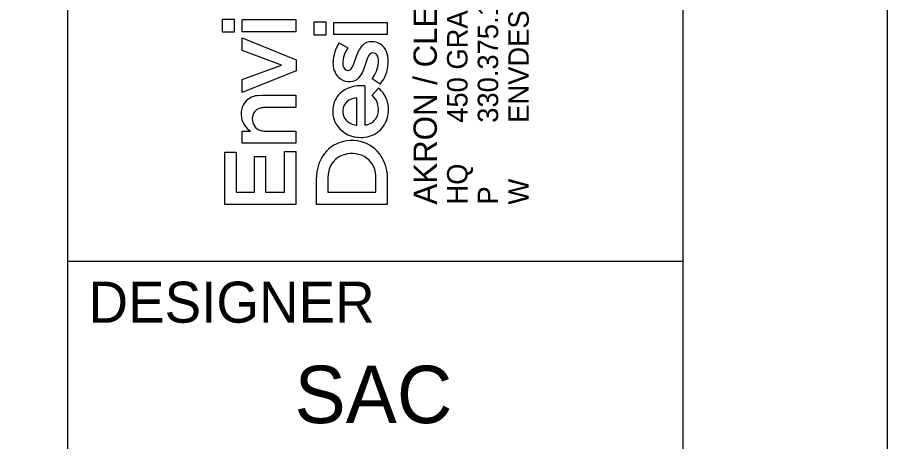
# Model space of a CAD drawing. Extents: x 0 to 34, y 0 to 22.
# Drawn here: x 31.877 to 34, y 2.06 to 3.094 of the extents above; entities that cross this region are included whole.
import ezdxf

# ---------------------------------------------------------------- set-up
doc = ezdxf.new("R2010")
doc.units = 0
for name, color, linetype in [('SH_Border', 7, 'Continuous'), ('SH_Cut_Line', 7, 'Continuous'), ('SH_Data', 7, 'Continuous')]:
    doc.layers.add(name, color=color, linetype=linetype)

msp = doc.modelspace()

# ---------------------------------------------------------------- linework, layer by layer
at = {"layer": 'SH_Border'}
for p, q in [((32, 0.5), (32, 21.5)), ((32, 2.5), (33.5, 2.5))]:
    msp.add_line(p, q, dxfattribs=at)
msp.add_lwpolyline([(1.5, 21.5), (33.5, 21.5), (33.5, 0.5), (1.5, 0.5)], close=True, dxfattribs=at)
at = {"layer": 'SH_Cut_Line'}
msp.add_lwpolyline([(0, 0), (34, 0), (34, 22), (0, 22)], close=True, dxfattribs=at)
at = {"layer": 'SH_Data'}
for p, q in [((32.3771, 3.0582), (32.3771, 3.0903)), ((32.3771, 3.0903), (32.4054, 3.0903)), ((32.4054, 3.0903), (32.4054, 3.0582)), ((32.4254, 3.0594), (32.4254, 3.0893)), ((32.4254, 3.0893), (32.5557, 3.0893)), ((32.5557, 3.0893), (32.5557, 3.0594)), ((32.6005, 3.0511), (32.6005, 3.0832)), ((32.6005, 3.0832), (32.6289, 3.0832)), ((32.6289, 3.0832), (32.6289, 3.0511)), ((32.6489, 3.0523), (32.6489, 3.0822)), ((32.6489, 3.0822), (32.7792, 3.0822)), ((32.7792, 3.0822), (32.7792, 3.0523)), ((32.4054, 3.0582), (32.3771, 3.0582)), ((32.5557, 3.0594), (32.4254, 3.0594)), ((32.4254, 3.0133), (32.4254, 3.0446)), ((32.4254, 3.0446), (32.5567, 2.9913)), ((32.6289, 3.0511), (32.6005, 3.0511)), ((32.7792, 3.0523), (32.6489, 3.0523)), ((32.6615, 3.0321), (32.6827, 3.0203)), ((32.5212, 2.978), (32.4254, 3.0133)), ((32.6967, 2.9787), (32.7048, 3.0026)), ((32.7048, 3.0026), (32.7104, 3.0153)), ((32.7334, 3.001), (32.7298, 2.9933)), ((32.4254, 2.9429), (32.5212, 2.978)), ((32.5567, 2.9913), (32.5567, 2.9644)), ((32.693, 2.9712), (32.6967, 2.9787)), ((32.7298, 2.9933), (32.7221, 2.9688)), ((32.5567, 2.9644), (32.4254, 2.9109)), ((32.7221, 2.9688), (32.7182, 2.9592)), ((32.4254, 2.9109), (32.4254, 2.9429)), ((32.7621, 2.9314), (32.742, 2.9447)), ((32.7245, 2.9275), (32.7246, 2.8319)), ((32.7423, 2.9046), (32.7577, 2.922)), ((32.4644, 2.904), (32.4729, 2.9044)), ((32.4729, 2.9044), (32.5557, 2.9044)), ((32.5557, 2.9044), (32.5557, 2.8746)), ((32.7049, 2.8318), (32.7049, 2.8983)), ((32.5557, 2.8746), (32.4814, 2.8746)), ((32.7036, 2.8317), (32.7049, 2.8318)), ((32.4254, 2.7875), (32.4254, 2.8173)), ((32.4254, 2.8173), (32.4455, 2.8173)), ((32.4822, 2.8173), (32.5557, 2.8173)), ((32.5557, 2.8173), (32.5557, 2.7876)), ((32.5557, 2.7876), (32.4254, 2.7875)), ((32.383, 2.6379), (32.383, 2.766)), ((32.383, 2.766), (32.4101, 2.766)), ((32.4101, 2.766), (32.4101, 2.6683)), ((32.5286, 2.6683), (32.5286, 2.7672)), ((32.5286, 2.7672), (32.5557, 2.7672)), ((32.5557, 2.7672), (32.5557, 2.6379)), ((32.455, 2.6683), (32.455, 2.7549)), ((32.455, 2.7549), (32.4822, 2.7549)), ((32.4822, 2.7549), (32.4822, 2.6683)), ((32.6064, 2.638), (32.6064, 2.704)), ((32.6347, 2.7118), (32.6341, 2.7023)), ((32.6341, 2.7023), (32.6341, 2.6684)), ((32.7515, 2.6683), (32.7515, 2.7024)), ((32.7785, 2.715), (32.7792, 2.7021)), ((32.7792, 2.7021), (32.7792, 2.638)), ((32.4101, 2.6683), (32.455, 2.6683)), ((32.4822, 2.6683), (32.5286, 2.6683)), ((32.6341, 2.6684), (32.7515, 2.6683)), ((32.5557, 2.6379), (32.383, 2.6379)), ((32.7792, 2.638), (32.6064, 2.638))]:
    msp.add_line(p, q, dxfattribs=at)
for points in [[(32.3771, 3.0582), (32.3771, 3.0903), (32.4054, 3.0903), (32.4054, 3.0582)], [(32.4254, 3.0594), (32.4254, 3.0893), (32.5557, 3.0893), (32.5557, 3.0594)], [(32.6005, 3.0511), (32.6005, 3.0832), (32.6289, 3.0832), (32.6289, 3.0511)], [(32.6489, 3.0523), (32.6489, 3.0822), (32.7792, 3.0822), (32.7792, 3.0523)], [(32.4254, 2.9109), (32.4254, 2.9429), (32.5212, 2.978), (32.4254, 3.0133), (32.4254, 3.0446), (32.5567, 2.9913), (32.5567, 2.9644)], [(32.383, 2.6379), (32.383, 2.766), (32.4101, 2.766), (32.4101, 2.6683), (32.455, 2.6683), (32.455, 2.7549), (32.4822, 2.7549), (32.4822, 2.6683), (32.5286, 2.6683), (32.5286, 2.7672), (32.5557, 2.7672), (32.5557, 2.6379)]]:
    msp.add_lwpolyline(points, close=True, dxfattribs=at)
for points in [[(32.6615, 3.0321), (32.6827, 3.0203)], [(32.693, 2.9712), (32.6967, 2.9787), (32.7048, 3.0026), (32.7104, 3.0153)], [(32.7334, 3.001), (32.7298, 2.9933), (32.7221, 2.9688), (32.7182, 2.9592)], [(32.7621, 2.9314), (32.742, 2.9447)], [(32.7245, 2.9275), (32.7246, 2.8319)], [(32.7423, 2.9046), (32.7577, 2.922)], [(32.4644, 2.904), (32.4729, 2.9044), (32.5557, 2.9044), (32.5557, 2.8746), (32.4814, 2.8746)], [(32.7036, 2.8317), (32.7049, 2.8318), (32.7049, 2.8983)], [(32.4254, 2.7875), (32.4254, 2.8173), (32.4455, 2.8173)], [(32.4822, 2.8173), (32.5557, 2.8173), (32.5557, 2.7876), (32.4254, 2.7875)], [(32.7785, 2.715), (32.7792, 2.7021), (32.7792, 2.638), (32.6064, 2.638)], [(32.6064, 2.638), (32.6064, 2.704)], [(32.6347, 2.7118), (32.6341, 2.7023), (32.6341, 2.6684), (32.7515, 2.6683), (32.7515, 2.7024)]]:
    msp.add_lwpolyline(points, dxfattribs=at)
for centre, radius, start, end in [((32.7364, 2.9826), 0.0897, 146.531, 178.7571), ((32.7364, 2.9826), 0.0897, 146.531, 178.7571), ((32.7452, 2.9789), 0.0749, 146.5112, 176.9101), ((32.7452, 2.9789), 0.0749, 146.5112, 176.9101), ((32.7466, 2.9971), 0.0405, 125.5118, 153.4159), ((32.7466, 2.9971), 0.0405, 125.5118, 153.4159), ((32.7406, 3.0026), 0.0326, 80.1719, 122.5197), ((32.7406, 3.0026), 0.0326, 80.1719, 122.5197), ((32.7428, 2.9982), 0.0367, 47.7934, 84.6892), ((32.7428, 2.9982), 0.0367, 47.7934, 84.6892), ((32.7379, 2.9946), 0.0427, 14.9966, 46.2063), ((32.7379, 2.9946), 0.0427, 14.9966, 46.2063), ((32.7438, 2.9963), 0.0114, 76.6609, 155.7053), ((32.7438, 2.9963), 0.0114, 76.6609, 155.7053), ((32.744, 2.9951), 0.0126, 21.5098, 78.5262), ((32.744, 2.9951), 0.0126, 21.5098, 78.5262), ((32.7259, 2.9877), 0.0321, 354.5726, 22.068), ((32.7259, 2.9877), 0.0321, 354.5726, 22.068), ((32.7104, 2.9867), 0.0712, 355.8306, 15.3914), ((32.7104, 2.9867), 0.0712, 355.8306, 15.3914), ((32.6967, 2.9824), 0.0501, 177.5366, 222.7932), ((32.6967, 2.9824), 0.0501, 177.5366, 222.7932), ((32.6931, 2.9823), 0.0228, 178.4747, 211.0868), ((32.6931, 2.9823), 0.0228, 178.4747, 211.0868), ((32.6825, 2.9915), 0.0757, 321.811, 354.7969), ((32.6825, 2.9915), 0.0757, 321.811, 354.7969), ((32.6895, 2.9882), 0.0922, 321.9777, 355.8738), ((32.6895, 2.9882), 0.0922, 321.9777, 355.8738), ((32.6833, 2.9767), 0.0115, 212.2368, 268.3777), ((32.6833, 2.9767), 0.0115, 212.2368, 268.3777), ((32.6834, 2.9759), 0.0107, 267.716, 333.7337), ((32.6834, 2.9759), 0.0107, 267.716, 333.7337), ((32.681, 2.9758), 0.0408, 308.0877, 335.9874), ((32.681, 2.9758), 0.0408, 308.0877, 335.9874), ((32.686, 2.9753), 0.0375, 225.9854, 302.4797), ((32.686, 2.9753), 0.0375, 225.9854, 302.4797), ((32.7024, 2.8691), 0.0558, 118.8308, 160.6244), ((32.7024, 2.8691), 0.0558, 118.8308, 160.6244), ((32.7152, 2.8441), 0.0838, 83.615, 118.2876), ((32.7152, 2.8441), 0.0838, 83.615, 118.2876), ((32.7174, 2.8717), 0.0644, 13.5336, 51.3615), ((32.7174, 2.8717), 0.0644, 13.5336, 51.3615), ((32.4635, 2.8626), 0.0402, 132.2219, 161.6818), ((32.4635, 2.8626), 0.0402, 132.2219, 161.6818), ((32.4687, 2.8543), 0.0499, 94.9696, 130.2225), ((32.4687, 2.8543), 0.0499, 94.9696, 130.2225), ((32.7005, 2.8663), 0.0298, 132.9851, 177.179), ((32.7005, 2.8663), 0.0298, 132.9851, 177.179), ((32.7079, 2.8561), 0.0424, 94.008, 130.8817), ((32.7079, 2.8561), 0.0424, 94.008, 130.8817), ((32.7038, 2.8656), 0.0549, 19.0357, 45.4406), ((32.7038, 2.8656), 0.0549, 19.0357, 45.4406), ((32.4787, 2.8582), 0.056, 162.2736, 187.7919), ((32.4787, 2.8582), 0.056, 162.2736, 187.7919), ((32.4748, 2.8487), 0.025, 103.6865, 182.2187), ((32.4748, 2.8487), 0.025, 103.6865, 182.2187), ((32.4811, 2.8286), 0.046, 89.6049, 105.3284), ((32.4811, 2.8286), 0.046, 89.6049, 105.3284), ((32.7104, 2.8661), 0.0644, 160.5201, 215.7831), ((32.7104, 2.8661), 0.0644, 160.5201, 215.7831), ((32.7017, 2.865), 0.0311, 175.0013, 223.283), ((32.7017, 2.865), 0.0311, 175.0013, 223.283), ((32.7107, 2.8697), 0.047, 344.6059, 17.007), ((32.7107, 2.8697), 0.047, 344.6059, 17.007), ((32.7064, 2.8692), 0.0758, 339.3542, 13.3785), ((32.7064, 2.8692), 0.0758, 339.3542, 13.3785), ((32.4703, 2.858), 0.0476, 188.962, 238.7037), ((32.4703, 2.858), 0.0476, 188.962, 238.7037), ((32.4773, 2.8456), 0.0276, 175.5854, 255.1439), ((32.4773, 2.8456), 0.0276, 175.5854, 255.1439), ((32.7224, 2.8671), 0.035, 288.0077, 343.5508), ((32.7224, 2.8671), 0.035, 288.0077, 343.5508), ((32.7125, 2.8705), 0.0687, 217.7452, 271.6543), ((32.7125, 2.8705), 0.0687, 217.7452, 271.6543), ((32.7089, 2.8736), 0.0423, 225.0619, 262.7974), ((32.7089, 2.8736), 0.0423, 225.0619, 262.7974), ((32.7247, 2.8522), 0.0202, 269.7003, 294.8711), ((32.7247, 2.8522), 0.0202, 269.7003, 294.8711), ((32.7189, 2.8652), 0.0626, 300.9427, 338.7323), ((32.7189, 2.8652), 0.0626, 300.9427, 338.7323), ((32.4818, 2.8595), 0.0422, 254.0916, 270.5284), ((32.4818, 2.8595), 0.0422, 254.0916, 270.5284), ((32.7155, 2.8724), 0.0706, 269.2048, 300.3341), ((32.7155, 2.8724), 0.0706, 269.2048, 300.3341), ((32.6923, 2.7079), 0.0864, 81.194, 125.9984), ((32.6923, 2.7079), 0.0864, 81.194, 125.9984), ((32.6946, 2.7113), 0.0827, 37.8521, 82.402), ((32.6946, 2.7113), 0.0827, 37.8521, 82.402), ((32.6939, 2.7089), 0.0865, 127.2362, 165.148), ((32.6939, 2.7089), 0.0865, 127.2362, 165.148), ((32.6928, 2.6986), 0.0639, 55.6727, 107.2093), ((32.6928, 2.6986), 0.0639, 55.6727, 107.2093), ((32.6859, 2.7057), 0.0931, 5.7333, 37.304), ((32.6859, 2.7057), 0.0931, 5.7333, 37.304), ((32.6889, 2.7078), 0.054, 106.1881, 157.3861), ((32.6889, 2.7078), 0.054, 106.1881, 157.3861), ((32.6929, 2.705), 0.0587, 357.4662, 52.2665), ((32.6929, 2.705), 0.0587, 357.4662, 52.2665), ((32.7143, 2.7028), 0.1078, 164.7861, 179.3704), ((32.7143, 2.7028), 0.1078, 164.7861, 179.3704), ((32.6983, 2.7039), 0.0641, 157.3571, 172.9275), ((32.6983, 2.7039), 0.0641, 157.3571, 172.9275)]:
    msp.add_arc(centre, radius, start, end, dxfattribs=at)

# ---------------------------------------------------------------- texts
for s, height, p in [('450 GRANT ST., AKRON, OH  44311', 0.049846, (32.9749, 2.8374)), ('AKRON / CLEVELAND / COLUMBUS', 0.056969, (32.9001, 2.638)), ('ENVDESIGNGROUP.COM', 0.049846, (33.1244, 2.8374)), ('330.375.1390', 0.049846, (33.0497, 2.8374)), ('HQ ', 0.04985, (32.9749, 2.638)), ('W', 0.0498, (33.1244, 2.638)), ('P', 0.0498, (33.0497, 2.638))]:
    msp.add_text(s, height=height, rotation=90, dxfattribs=at).set_placement(p)
for s, height, p in [('DESIGNER', 0.1, (32.05, 2.35)), ('SAC', 0.14, (32.5528, 2.105))]:
    msp.add_text(s, height=height, dxfattribs=at).set_placement(p)

doc.saveas('drawing.dxf')
